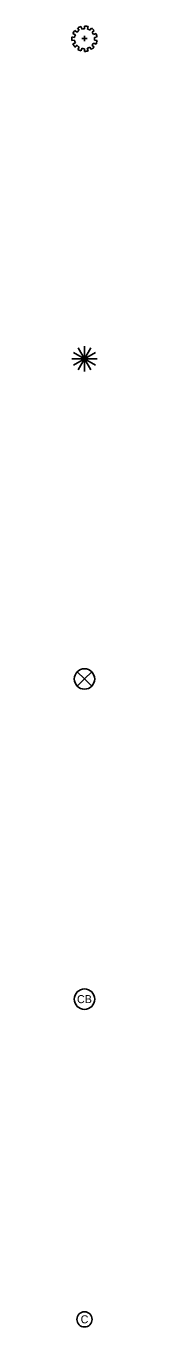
# Model space of a CAD drawing. Extents: x 98 to 2902, y -6 to 903.
# Drawn here: x 298 to 302, y 448.8 to 652 of the extents above; entities that cross this region are included whole.
import ezdxf

# ---------------------------------------------------------------- set-up
doc = ezdxf.new("R2010")
doc.units = 0
for name, color, linetype in [('B-SAMP-CORE', 7, 'Continuous'), ('V-COMM-EQPM', 7, 'Continuous'), ('V-SITE-VEGE', 7, 'Continuous'), ('V-STRM-DEVC', 7, 'Continuous')]:
    doc.layers.add(name, color=color, linetype=linetype)

msp = doc.modelspace()

# ---------------------------------------------------------------- linework, layer by layer
at = {"layer": 'B-SAMP-CORE'}
for p, q in [((298.87, 551.13), (300, 550)), ((298.87, 551.13), (298.87, 551.13)), ((301.13, 551.13), (300, 550)), ((300, 550), (298.87, 548.87)), ((300, 550), (301.13, 548.87))]:
    msp.add_line(p, q, dxfattribs=at)
msp.add_circle((300, 550), 1.59, dxfattribs=at)
for start, end in [(134.9951, 225.0116), (315.0076, 44.9844)]:
    msp.add_arc((300, 550), 1.59, start, end, dxfattribs=at)
at = {"layer": 'V-COMM-EQPM'}
msp.add_circle((300, 450), 1.19, dxfattribs=at)
at = {"layer": 'V-SITE-VEGE'}
for p, q in [((298.03, 650.25), (298.46, 650.18)), ((298.58, 650.61), (298.19, 650.78)), ((298.49, 651.26), (298.81, 650.98)), ((299.17, 651.3), (298.93, 651.65)), ((299.46, 651.89), (299.56, 651.47)), ((300, 651.53), (300.01, 651.96)), ((300, 650.42), (300, 649.58)), ((300.57, 651.88), (300.45, 651.47)), ((300.84, 651.29), (301.08, 651.64)), ((301.51, 651.27), (301.19, 650.99)), ((301.42, 650.62), (301.8, 650.82)), ((301.97, 650.25), (301.54, 650.19)), ((298.46, 649.76), (298.04, 649.69)), ((298.19, 649.16), (298.58, 649.35)), ((298.83, 648.96), (298.5, 648.68)), ((298.94, 648.3), (299.15, 648.68)), ((299.58, 648.48), (299.46, 648.07)), ((299.58, 650), (300.42, 650)), ((300, 647.99), (300, 648.42)), ((300.43, 648.49), (300.56, 648.08)), ((301.08, 648.31), (300.85, 648.68)), ((301.17, 648.95), (301.5, 648.68)), ((301.81, 649.15), (301.41, 649.31)), ((301.54, 649.75), (301.97, 649.7)), ((300, 600), (299.01, 601.72)), ((300, 601.98), (300, 600)), ((300, 600), (300.99, 601.72)), ((298.02, 600), (300, 600)), ((300, 600), (298.28, 600.99)), ((300, 600), (298.28, 599.01)), ((300, 600), (299.01, 598.28)), ((300, 600), (301.72, 600.99)), ((300, 600), (300.99, 598.28)), ((300, 600), (301.72, 599.01)), ((300, 600), (300, 598.02)), ((300, 600), (301.98, 600))]:
    msp.add_line(p, q, dxfattribs=at)
for radius, start, end in [(1.98, 172.27, 188.583), (1.98, 139.7777, 156.0738), (1.56, 156.0557, 172.7558), (1.56, 122.254, 140.086), (1.98, 105.972, 122.5562), (1.56, 89.9461, 106.3473), (1.98, 73.2952, 89.5718), (1.56, 57.451, 73.0843), (1.98, 40.7122, 57.1166), (1.56, 24.4529, 40.4774), (1.56, 351.5431, 7.6203), (1.98, 7.9671, 24.8625), (1.98, 204.5394, 220.9852), (1.56, 188.0619, 204.0332), (1.56, 221.2062, 236.7795), (1.98, 237.6108, 254.1981), (1.56, 254.31, 270.043), (1.98, 270.0356, 286.342), (1.56, 285.9559, 303.0564), (1.98, 302.8434, 319.0222), (1.56, 318.6432, 334.5795), (1.98, 335.3123, 351.7042)]:
    msp.add_arc((300, 649.98), radius, start, end, dxfattribs=at)
at = {"layer": 'V-STRM-DEVC'}
msp.add_circle((300, 500), 1.59, dxfattribs=at)

# ---------------------------------------------------------------- texts
at = {"layer": 'V-COMM-EQPM'}
msp.add_text('C', height=1.25, dxfattribs=at).set_placement((299.4, 449.38))
at = {"layer": 'V-STRM-DEVC'}
msp.add_text('CB', height=1.25, dxfattribs=at).set_placement((298.83, 499.38))

doc.saveas('drawing.dxf')
